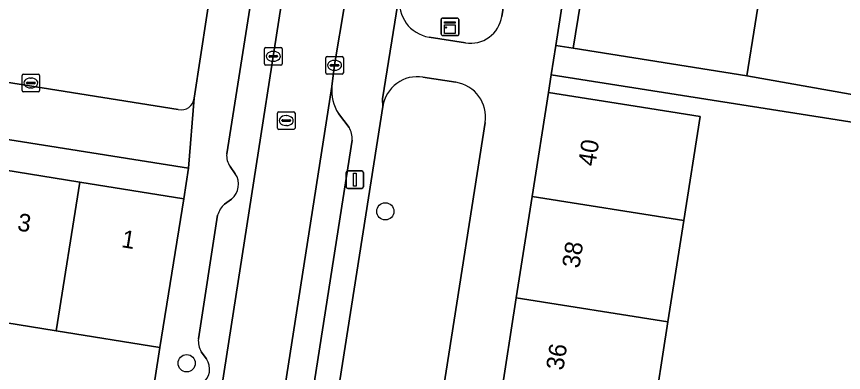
# Model space of a CAD drawing. Extents: x 163008 to 163854, y 382777 to 383982.
# Drawn here: x 163263.83 to 163310.89, y 383161.59 to 383181.81 of the extents above; entities that cross this region are included whole.
import ezdxf

# ---------------------------------------------------------------- set-up
doc = ezdxf.new("R2010")
doc.units = 0
for name, color, linetype in [('IMGEO_Boom', 7, 'Continuous'), ('IMGEO_Erf', 7, 'Continuous'), ('IMGEO_Groenvoorziening', 7, 'Continuous'), ('IMGEO_Kast', 7, 'Continuous'), ('IMGEO_Kolk', 7, 'Continuous'), ('IMGEO_Lichtmast', 7, 'Continuous'), ('IMGEO_Muur', 7, 'Continuous'), ('IMGEO_Pand', 7, 'Continuous'), ('IMGEO_Pand_nummerreeks', 7, 'Continuous'), ('IMGEO_Parkeervlak_open', 7, 'Continuous'), ('IMGEO_Rijbaan_lokaal_open', 7, 'Continuous'), ('IMGEO_Rioolput', 7, 'Continuous'), ('IMGEO_Voetpad_open', 7, 'Continuous')]:
    doc.layers.add(name, color=color, linetype=linetype)

msp = doc.modelspace()

# ---------------------------------------------------------------- linework, layer by layer
at = {"layer": 'IMGEO_Boom'}
for centre in [(163284.817, 383170.741), (163273.512, 383162.108)]:
    msp.add_circle(centre, 0.489, dxfattribs=at)
at = {"layer": 'IMGEO_Erf'}
for points in [[(163319.733, 383214.6), (163308.327, 383216.34), (163307.391, 383210.439), (163310.885, 383209.891), (163309.982, 383204.131), (163306.478, 383204.681), (163305.565, 383198.922), (163304.653, 383193.165), (163307.379, 383192.737), (163306.476, 383186.977), (163306.759, 383186.933), (163306.746, 383186.853), (163306.687, 383186.496), (163306.339, 383184.371), (163305.399, 383178.444), (163318.007, 383176.201)], [(163313.908, 383175.415), (163294.265, 383178.498), (163294.107, 383177.489), (163299.047, 383176.714), (163302.735, 383176.135), (163301.807, 383170.226), (163300.903, 383164.465), (163299.999, 383158.703)], [(163270.324, 383152.219), (163271.991, 383163.012), (163266.087, 383163.957), (163260.334, 383164.877), (163254.582, 383165.797), (163248.829, 383166.718), (163242.926, 383167.662), (163243.899, 383173.74), (163244.278, 383176.111), (163250.181, 383175.167), (163255.934, 383174.246), (163261.686, 383173.326), (163267.439, 383172.405), (163273.342, 383171.461), (163273.609, 383173.196), (163244.524, 383177.794), (163244.095, 383177.862), (163243.847, 383176.174), (163243.502, 383173.822), (163241.409, 383159.573)]]:
    msp.add_lwpolyline(points, dxfattribs=at)
msp.add_lwpolyline([(163295.918, 383182.577), (163294.93, 383182.733), (163294.527, 383180.165), (163295.512, 383180.01)], close=True, dxfattribs=at)
at = {"layer": 'IMGEO_Groenvoorziening'}
for points in [[(163291.443, 383181.812), (163296.484, 383213.615)], [(163273.94, 383177.173), (163276.108, 383191.281)], [(163247.162, 383180.646), (163273.036, 383176.528)], [(163287.309, 383180.645), (163289.383, 383180.316)], [(163288.836, 383178.075), (163286.959, 383178.371)], [(163284.671, 383176.706), (163280.237, 383148.453), (163286.065, 383147.534), (163290.5, 383175.79)]]:
    msp.add_lwpolyline(points, dxfattribs=at)
for centre, radius, start, end in [((163287.622, 383182.621), 2, 171.3088, 260.9849), ((163289.666, 383182.093), 1.799, 260.9577, 351.0176), ((163286.646, 383176.396), 1.999, 81.0012, 171.0863), ((163288.525, 383176.1), 1.999, 351.0816, 81.0446), ((163273.193, 383177.264), 0.753, 257.9786, 353.0367)]:
    msp.add_arc(centre, radius, start, end, dxfattribs=at)
at = {"layer": 'IMGEO_Kast'}
for p, q in [((163288, 383180.803), (163288, 383181.644)), ((163288, 383181.644), (163288, 383180.803)), ((163288.075, 383181.728), (163288.916, 383181.728)), ((163288.916, 383181.728), (163288.075, 383181.728)), ((163289, 383181.653), (163289, 383180.812)), ((163289, 383180.812), (163289, 383181.653)), ((163288.925, 383180.728), (163288.084, 383180.728)), ((163288.084, 383180.728), (163288.925, 383180.728))]:
    msp.add_line(p, q, dxfattribs=at)
for points in [[(163288.195, 383181.518), (163288.795, 383181.518), (163288.795, 383181.433), (163288.195, 383181.433), (163288.195, 383181.518)], [(163288.195, 383181.343), (163288.795, 383181.343), (163288.795, 383180.854), (163288.195, 383180.854), (163288.195, 383181.343)]]:
    msp.add_lwpolyline(points, dxfattribs=at)
msp.add_circle((163288.279, 383181.192), 0.0377, dxfattribs=at)
for centre, start, end in [((163288.078, 383181.65), 92.4484, 184.2845), ((163288.078, 383181.65), 92.4484, 184.2845), ((163288.922, 383181.65), 2.4484, 94.2845), ((163288.922, 383181.65), 2.4484, 94.2845), ((163288.078, 383180.806), 182.4484, 274.2845), ((163288.078, 383180.806), 182.4484, 274.2845), ((163288.922, 383180.806), 272.4484, 4.2845), ((163288.922, 383180.806), 272.4484, 4.2845)]:
    msp.add_arc(centre, 0.0779, start, end, dxfattribs=at)
at = {"layer": 'IMGEO_Kolk'}
for p, q in [((163277.943, 383179.125), (163277.943, 383179.977)), ((163278.018, 383180.051), (163278.87, 383180.051)), ((163278.944, 383179.977), (163278.944, 383179.125)), ((163278.202, 383179.545), (163278.202, 383179.557)), ((163278.64, 383179.508), (163278.242, 383179.508)), ((163278.245, 383179.594), (163278.643, 383179.594)), ((163278.431, 383179.831), (163278.456, 383179.831)), ((163278.686, 383179.557), (163278.686, 383179.545)), ((163281.428, 383178.613), (163281.428, 383179.465)), ((163281.503, 383179.539), (163282.355, 383179.539)), ((163282.429, 383179.465), (163282.429, 383178.613)), ((163278.87, 383179.051), (163278.018, 383179.051)), ((163278.454, 383179.271), (163278.429, 383179.271)), ((163281.687, 383179.033), (163281.687, 383179.045)), ((163282.125, 383178.996), (163281.727, 383178.996)), ((163281.73, 383179.082), (163282.128, 383179.082)), ((163281.916, 383179.319), (163281.941, 383179.319)), ((163282.171, 383179.045), (163282.171, 383179.033)), ((163264.143, 383177.613), (163264.143, 383178.465)), ((163264.218, 383178.539), (163265.07, 383178.539)), ((163265.144, 383178.465), (163265.144, 383177.613)), ((163282.355, 383178.539), (163281.503, 383178.539)), ((163281.939, 383178.759), (163281.914, 383178.759)), ((163264.402, 383178.033), (163264.402, 383178.045)), ((163264.84, 383177.996), (163264.442, 383177.996)), ((163264.445, 383178.082), (163264.843, 383178.082)), ((163264.631, 383178.319), (163264.656, 383178.319)), ((163264.886, 383178.045), (163264.886, 383178.033)), ((163265.07, 383177.539), (163264.218, 383177.539)), ((163264.654, 383177.759), (163264.629, 383177.759))]:
    msp.add_line(p, q, dxfattribs=at)
for points in [[(163277.943, 383179.125), (163277.943, 383179.977)], [(163278.018, 383180.051), (163278.87, 383180.051)], [(163278.944, 383179.977), (163278.944, 383179.125)], [(163281.428, 383178.613), (163281.428, 383179.465)], [(163281.503, 383179.539), (163282.355, 383179.539)], [(163282.429, 383179.465), (163282.429, 383178.613)], [(163278.87, 383179.051), (163278.018, 383179.051)], [(163264.143, 383177.613), (163264.143, 383178.465)], [(163264.218, 383178.539), (163265.07, 383178.539)], [(163265.144, 383178.465), (163265.144, 383177.613)], [(163282.355, 383178.539), (163281.503, 383178.539)], [(163265.07, 383177.539), (163264.218, 383177.539)]]:
    msp.add_lwpolyline(points, dxfattribs=at)
for centre, radius, start, end in [((163278.02, 383179.975), 0.0765, 91.552, 178.448), ((163278.02, 383179.975), 0.0765, 91.552, 178.448), ((163278.868, 383179.975), 0.0765, 1.552, 88.448), ((163278.868, 383179.975), 0.0765, 1.552, 88.448), ((163278.242, 383179.554), 0.0403, 85.8775, 175.7526), ((163278.239, 383179.544), 0.0366, 178.938, 274.7102), ((163278.643, 383179.551), 0.043, 264.8664, 352.4533), ((163278.647, 383179.556), 0.0386, 1.7309, 96.639), ((163281.505, 383179.463), 0.0765, 91.552, 178.448), ((163281.505, 383179.463), 0.0765, 91.552, 178.448), ((163282.353, 383179.463), 0.0765, 1.552, 88.448), ((163282.353, 383179.463), 0.0765, 1.552, 88.448), ((163278.02, 383179.127), 0.0765, 181.552, 268.448), ((163278.02, 383179.127), 0.0765, 181.552, 268.448), ((163278.868, 383179.127), 0.0765, 271.552, 358.448), ((163278.868, 383179.127), 0.0765, 271.552, 358.448), ((163281.727, 383179.042), 0.0403, 85.8775, 175.7526), ((163281.724, 383179.032), 0.0366, 178.938, 274.7102), ((163282.128, 383179.039), 0.043, 264.8664, 352.4533), ((163282.132, 383179.044), 0.0386, 1.7309, 96.639), ((163264.22, 383178.463), 0.0765, 91.552, 178.448), ((163264.22, 383178.463), 0.0765, 91.552, 178.448), ((163265.068, 383178.463), 0.0765, 1.552, 88.448), ((163265.068, 383178.463), 0.0765, 1.552, 88.448), ((163281.505, 383178.615), 0.0765, 181.552, 268.448), ((163281.505, 383178.615), 0.0765, 181.552, 268.448), ((163282.353, 383178.615), 0.0765, 271.552, 358.448), ((163282.353, 383178.615), 0.0765, 271.552, 358.448), ((163264.442, 383178.042), 0.0403, 85.8775, 175.7526), ((163264.439, 383178.032), 0.0366, 178.938, 274.7102), ((163264.843, 383178.039), 0.043, 264.8664, 352.4533), ((163264.847, 383178.044), 0.0386, 1.7309, 96.639), ((163264.22, 383177.615), 0.0765, 181.552, 268.448), ((163264.22, 383177.615), 0.0765, 181.552, 268.448), ((163265.068, 383177.615), 0.0765, 271.552, 358.448), ((163265.068, 383177.615), 0.0765, 271.552, 358.448)]:
    msp.add_arc(centre, radius, start, end, dxfattribs=at)
for centre, major_axis, ratio, start_param, end_param in [((163278.43, 383179.551), (-0.387, 0.002), 0.722429, 4.712389, 7.853982), ((163278.455, 383179.551), (-0.39, 0.002), 0.717154, 1.570796, 4.712389), ((163281.915, 383179.039), (-0.387, 0.002), 0.722429, 4.712389, 7.853982), ((163281.94, 383179.039), (-0.39, 0.002), 0.717154, 1.570796, 4.712389), ((163264.63, 383178.039), (-0.387, 0.002), 0.722429, 4.712389, 7.853982), ((163264.655, 383178.039), (-0.39, 0.002), 0.717154, 1.570796, 4.712389)]:
    msp.add_ellipse(centre, major_axis=major_axis, ratio=ratio, start_param=start_param, end_param=end_param, dxfattribs=at)
at = {"layer": 'IMGEO_Lichtmast'}
for p, q in [((163282.587, 383172.14), (163282.587, 383172.94)), ((163282.587, 383172.94), (163282.587, 383172.14)), ((163282.687, 383173.04), (163283.477, 383173.04)), ((163283.477, 383173.04), (163282.687, 383173.04)), ((163283.577, 383172.94), (163283.577, 383172.14)), ((163283.577, 383172.14), (163283.577, 383172.94)), ((163283.477, 383172.04), (163282.687, 383172.04)), ((163282.687, 383172.04), (163283.477, 383172.04))]:
    msp.add_line(p, q, dxfattribs=at)
msp.add_lwpolyline([(163283.007, 383172.915), (163283.157, 383172.915), (163283.157, 383172.165), (163283.007, 383172.165), (163283.007, 383172.915)], dxfattribs=at)
for centre, start, end in [((163282.687, 383172.94), 90, 180), ((163282.687, 383172.94), 90, 180), ((163283.477, 383172.94), 0, 90), ((163283.477, 383172.94), 360, 90), ((163282.687, 383172.14), 180, 270), ((163282.687, 383172.14), 180, 270), ((163283.477, 383172.14), 270, 0), ((163283.477, 383172.14), 270, 0)]:
    msp.add_arc(centre, 0.1, start, end, dxfattribs=at)
at = {"layer": 'IMGEO_Muur'}
msp.add_lwpolyline([(163271.991, 383163.012), (163270.324, 383152.219)], dxfattribs=at)
at = {"layer": 'IMGEO_Pand'}
for points in [[(163306.339, 383184.371), (163306.687, 383186.496), (163306.746, 383186.853), (163306.759, 383186.933), (163306.476, 383186.977), (163303.74, 383187.407), (163295.867, 383188.642), (163294.93, 383182.733), (163295.918, 383182.577), (163295.512, 383180.01), (163305.399, 383178.444)], [(163293.179, 383171.58), (163301.807, 383170.226), (163302.735, 383176.135), (163299.047, 383176.714), (163294.107, 383177.489)], [(163266.087, 383163.957), (163267.439, 383172.405), (163261.686, 383173.326), (163260.334, 383164.877)], [(163266.087, 383163.957), (163271.991, 383163.012), (163273.342, 383171.461), (163267.439, 383172.405)], [(163292.275, 383165.819), (163300.903, 383164.465), (163301.807, 383170.226), (163293.179, 383171.58)], [(163292.275, 383165.819), (163291.371, 383160.057), (163299.999, 383158.703), (163300.903, 383164.465)]]:
    msp.add_lwpolyline(points, close=True, dxfattribs=at)
at = {"layer": 'IMGEO_Parkeervlak_open'}
for points in [[(163271.119, 383143.834), (163269.499, 383133.678), (163271.253, 383133.395), (163280.323, 383191.611), (163278.747, 383191.863), (163278.555, 383191.425), (163275.791, 383174.012)], [(163281.778, 383177.835), (163274.739, 383132.832), (163274.214, 383129.473), (163274.189, 383129.31), (163272.691, 383119.736)], [(163282.753, 383175.514), (163282.148, 383176.307)], [(163274.685, 383122.106), (163282.934, 383174.782)], [(163275.98, 383173.284), (163276.28, 383172.879)], [(163276.064, 383171.439), (163275.662, 383171.143)], [(163275.275, 383170.517), (163274.18, 383163.502)], [(163274.339, 383162.762), (163274.639, 383162.355)]]:
    msp.add_lwpolyline(points, dxfattribs=at)
for centre, radius, start, end in [((163284.255, 383177.626), 2.486, 175.175, 212.0489), ((163281.666, 383174.857), 1.27, 356.6239, 31.1538), ((163276.915, 383173.915), 1.128, 175.0846, 214.0225), ((163275.383, 383172.277), 1.08, 309.1035, 33.835), ((163276.454, 383170.221), 1.216, 130.6564, 165.894), ((163275.443, 383163.386), 1.269, 174.7709, 209.4821), ((163273.801, 383161.779), 1.017, 305.9492, 34.5024)]:
    msp.add_arc(centre, radius, start, end, dxfattribs=at)
at = {"layer": 'IMGEO_Rijbaan_lokaal_open'}
msp.add_lwpolyline([(163280.323, 383191.611), (163271.253, 383133.395), (163274.739, 383132.832), (163281.778, 383177.835), (163281.931, 383179.059), (163282.521, 383182.549), (163283.842, 383191.049)], close=True, dxfattribs=at)
at = {"layer": 'IMGEO_Rioolput'}
for p, q in [((163278.679, 383175.474), (163278.679, 383176.326)), ((163278.754, 383176.4), (163279.606, 383176.4)), ((163279.167, 383176.18), (163279.192, 383176.18)), ((163279.68, 383176.326), (163279.68, 383175.474)), ((163278.938, 383175.894), (163278.938, 383175.906)), ((163279.376, 383175.857), (163278.978, 383175.857)), ((163278.981, 383175.943), (163279.379, 383175.943)), ((163279.422, 383175.906), (163279.422, 383175.894)), ((163279.606, 383175.4), (163278.754, 383175.4)), ((163279.19, 383175.62), (163279.165, 383175.62))]:
    msp.add_line(p, q, dxfattribs=at)
for points in [[(163278.679, 383175.474), (163278.679, 383176.326)], [(163278.754, 383176.4), (163279.606, 383176.4)], [(163279.68, 383176.326), (163279.68, 383175.474)], [(163279.606, 383175.4), (163278.754, 383175.4)]]:
    msp.add_lwpolyline(points, dxfattribs=at)
for centre, radius, start, end in [((163278.756, 383176.324), 0.0765, 91.552, 178.448), ((163278.756, 383176.324), 0.0765, 91.552, 178.448), ((163279.604, 383176.324), 0.0765, 1.552, 88.448), ((163279.604, 383176.324), 0.0765, 1.552, 88.448), ((163278.978, 383175.903), 0.0403, 85.8775, 175.7526), ((163278.975, 383175.893), 0.0366, 178.938, 274.7102), ((163279.379, 383175.9), 0.043, 264.8664, 352.4533), ((163279.383, 383175.905), 0.0386, 1.7309, 96.639), ((163278.756, 383175.476), 0.0765, 181.552, 268.448), ((163278.756, 383175.476), 0.0765, 181.552, 268.448), ((163279.604, 383175.476), 0.0765, 271.552, 358.448), ((163279.604, 383175.476), 0.0765, 271.552, 358.448)]:
    msp.add_arc(centre, radius, start, end, dxfattribs=at)
for centre, major_axis, ratio, start_param, end_param in [((163279.166, 383175.9), (-0.387, 0.002), 0.722429, 4.712389, 7.853982), ((163279.191, 383175.9), (-0.39, 0.002), 0.717154, 1.570796, 4.712389)]:
    msp.add_ellipse(centre, major_axis=major_axis, ratio=ratio, start_param=start_param, end_param=end_param, dxfattribs=at)
at = {"layer": 'IMGEO_Voetpad_open'}
for points in [[(163287.225, 383235.912), (163287.268, 383236.188), (163288.351, 383243.343), (163288.604, 383245.855), (163288.916, 383248.053), (163283.447, 383248.694), (163283.291, 383247.605), (163285.113, 383246.694), (163284.577, 383243.244), (163283.726, 383237.452), (163283.138, 383233.704), (163281.914, 383225.899), (163281.271, 383221.8), (163281.061, 383220.467), (163281.06, 383220.463), (163278.636, 383205.006), (163277.379, 383197.145), (163277.094, 383195.491), (163276.108, 383191.281), (163273.94, 383177.173), (163273.609, 383173.196), (163273.342, 383171.461), (163271.991, 383163.012), (163270.324, 383152.219)], [(163284.671, 383176.706), (163284.666, 383177.145), (163285.538, 383182.562), (163285.645, 383182.923), (163290.673, 383214.627), (163291.719, 383220.383), (163291.889, 383221.504), (163292.497, 383225.517), (163293.584, 383232.329), (163294.174, 383236.034), (163295.019, 383241.608), (163295.515, 383245.185), (163297.157, 383245.389), (163297.404, 383246.677), (163292.509, 383247.462), (163292.347, 383246.561), (163289.218, 383225.695), (163289.711, 383225.617), (163289.114, 383221.85), (163288.621, 383221.928), (163288.503, 383221.183), (163288.335, 383219.963)], [(163287.753, 383137.011), (163288.658, 383142.773), (163289.562, 383148.534), (163290.466, 383154.296), (163291.371, 383160.057), (163292.275, 383165.819), (163293.179, 383171.58), (163294.107, 383177.489), (163294.265, 383178.498), (163294.527, 383180.165), (163294.93, 383182.733), (163295.867, 383188.642), (163296.779, 383194.4), (163297.692, 383200.158), (163298.605, 383205.916), (163299.517, 383211.674), (163300.454, 383217.582), (163300.683, 383219.028), (163300.448, 383219.057), (163298.028, 383219.424), (163291.719, 383220.383), (163290.673, 383214.627)], [(163296.484, 383213.615), (163291.443, 383181.812)], [(163275.791, 383174.012), (163278.555, 383191.425), (163278.747, 383191.863), (163278.952, 383192.046), (163279.371, 383192.356)], [(163285.645, 383182.923), (163285.538, 383182.562), (163284.666, 383177.145), (163284.671, 383176.706)], [(163282.521, 383182.549), (163281.931, 383179.059), (163281.778, 383177.835)], [(163273.036, 383176.528), (163247.162, 383180.646)], [(163289.383, 383180.316), (163287.309, 383180.645)], [(163318.007, 383176.201), (163305.399, 383178.444), (163295.512, 383180.01), (163294.527, 383180.165), (163294.265, 383178.498), (163313.908, 383175.415)], [(163286.959, 383178.371), (163288.836, 383178.075)], [(163244.524, 383177.794), (163273.609, 383173.196), (163273.94, 383177.173)], [(163265.57, 383054.888), (163269.985, 383082.335), (163275.662, 383081.422), (163275.873, 383083.085), (163270.193, 383083.981), (163274.68, 383112.429), (163274.673, 383112.705), (163275.529, 383118.456), (163279.973, 383146.774), (163285.801, 383145.855), (163286.065, 383147.534), (163280.237, 383148.453), (163284.671, 383176.706)], [(163282.148, 383176.307), (163282.753, 383175.514)], [(163290.5, 383175.79), (163286.065, 383147.534), (163285.801, 383145.855), (163281.366, 383117.602)], [(163282.934, 383174.782), (163274.685, 383122.106)], [(163276.28, 383172.879), (163275.98, 383173.284)], [(163275.662, 383171.143), (163276.064, 383171.439)], [(163274.18, 383163.502), (163275.275, 383170.517)], [(163274.639, 383162.355), (163274.339, 383162.762)]]:
    msp.add_lwpolyline(points, dxfattribs=at)
for centre, radius, start, end in [((163287.622, 383182.621), 2, 171.3088, 260.9849), ((163289.666, 383182.093), 1.799, 260.9577, 351.0176), ((163286.646, 383176.396), 1.999, 81.0012, 171.0863), ((163288.525, 383176.1), 1.999, 351.0816, 81.0446), ((163284.255, 383177.626), 2.486, 175.175, 212.0489), ((163273.193, 383177.264), 0.753, 257.9786, 353.0367), ((163281.666, 383174.857), 1.27, 356.6239, 31.1538), ((163276.915, 383173.915), 1.128, 175.0846, 214.0225), ((163275.383, 383172.277), 1.08, 309.1035, 33.835), ((163276.454, 383170.221), 1.216, 130.6564, 165.894), ((163275.443, 383163.386), 1.269, 174.7709, 209.4821), ((163273.801, 383161.779), 1.017, 305.9492, 34.5024)]:
    msp.add_arc(centre, radius, start, end, dxfattribs=at)

# ---------------------------------------------------------------- texts
at = {"layer": 'IMGEO_Pand_nummerreeks'}
for s, rotation, p in [('40', 81.079, (163296.765, 383173.267)), ('3', 350.9102, (163263.833, 383169.66)), ('1', 350.9102, (163269.758, 383168.712)), ('38', 81.079, (163295.854, 383167.468)), ('36', 81.079, (163294.944, 383161.665))]:
    msp.add_text(s, height=1, rotation=rotation, dxfattribs=at).set_placement(p)

doc.saveas('drawing.dxf')
